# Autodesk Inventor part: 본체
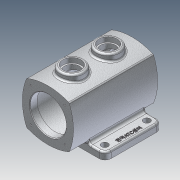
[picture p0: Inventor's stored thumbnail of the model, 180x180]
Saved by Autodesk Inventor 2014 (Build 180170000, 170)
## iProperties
Created: 2013-02
Part Number: 본체
Document SubType Name: Modeling
Designer: 한국산업디자인학원[gmhk.co.kr]
Density: 1 g/cm^3
Material: 일반
Appearance: _시험_알루미늄 표면거칠기
Author: 한국산업디자인학원[gmhk.co.kr]
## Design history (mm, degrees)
sketch "스케치1"
  geometry: L1 (-65, 55)-(65, 55); L2 (65, 55)-(65, -40); L3 (65, -40)-(-65, -40); L4 (-65, -40)-(-65, 55); 2 further points
  constraints: 8 end point, 2 parallel, 1 horizontal, 1 midpoint, 1 perpendicular, 1 vertical alignment
  dimensions: "d0" = 130 distance of L2.end L3.end; "d1" = 95 distance of L1.end L2.end; "d47" = 40 distance from line of L3 point (0, 0)
extrude "돌출1" new body sketch "스케치1" distance "d2" = 12; taper "d3" = 0 deg
sketch "스케치2"
  geometry: L1 (-35.355, 85.355)-(35.355, 85.355); L2 (35.355, 85.355)-(35.355, 14.645); L3 (35.355, 14.645)-(-35.355, 14.645); L4 (-35.355, 14.645)-(-35.355, 85.355); L5 (35.355, 85.355)-(-35.355, 14.645); L6 (65, 0)-(-65, 0) reference; A1 r 91.05 centre (0, 1.45) between (35.355, 85.355) and (-35.355, 85.355); A2 r 91.05 centre (-48.55, 50) between (35.355, 14.645) and (35.355, 85.355); A3 r 91.05 centre (0, 98.55) between (-35.355, 14.645) and (35.355, 14.645); A4 r 91.05 centre (48.55, 50) between (-35.355, 85.355) and (-35.355, 14.645); 3 further points
  constraints: 10 end point, 8 point on circle, 4 centre point, 3 equal radius, 2 midpoint, 2 parallel, 2 perpendicular, 1 horizontal, 1 vertical alignment
  dimensions: "d4" = 50 distance from line of point (0, 50) L6; "d5" = 50 distance of L1.start point (0, 50); "d6" = 85 dimension on A2 A4
extrude "돌출2" join sketch "스케치2" stored distance "d7" = 140; taper "d8" = 0 deg
sketch "스케치3"
  geometry: L1 (28.27, 12)-(65, 12) reference; L2 (-65, 12)-(-28.27, 12) reference; A1 r 91.05 centre (0, 98.55) between (-35.355, 14.645) and (35.355, 14.645) reference; A2 r 91.05 centre (48.55, 50) between (-35.355, 85.355) and (-35.355, 14.645) reference; A3 r 91.05 centre (-48.55, 50) between (35.355, 14.645) and (35.355, 85.355) reference; A4 r 5 centre (-41.653, 17) between (-41.653, 12) and (-36.957, 18.718); A5 r 5 centre (41.653, 17) between (36.957, 18.718) and (41.653, 12); 1 further point
  constraints: 6 point on circle, 4 tangent, 2 centre point, 2 point on line, 1 equal radius
  dimensions: "d9" = 5 radius of A5
extrude "돌출3" join sketch "스케치3" stored distance "d10" = 120; taper "d11" = 0 deg
fillet "모깎기1" dims "d12" = 3
fillet "모깎기2" dims "d13" = 10
fillet "모깎기3" dims "d14" = 3
sketch "스케치4"
  geometry: L1 (-70, 84.185)-(-70, 85.839) reference; L2 (-70, 15.815)-(-70, 84.185) reference; L3 (-70, 14.161)-(-70, 15.815) reference; L4 (-70, 14.161)-(-70, 14.161) reference; L5 (-70, 15.815)-(-70, 14.161) reference; L6 (-70, 84.185)-(-70, 15.815) reference; L7 (-70, 85.839)-(-70, 84.185) reference; L8 (-70, 85.839)-(-70, 85.839) reference; L9 (70, 15.815)-(70, 14.161) reference; L10 (70, 84.185)-(70, 15.815) reference; L11 (70, 85.839)-(70, 84.185) reference; L12 (70, 85.839)-(70, 85.839) reference; L13 (70, 84.185)-(70, 85.839) reference; L14 (70, 15.815)-(70, 84.185) reference; L15 (70, 14.161)-(70, 15.815) reference; L16 (70, 14.161)-(70, 14.161) reference; L17 (-70, 50)-(70, 50); L18 (-70, 80)-(-58, 80); L19 (-58, 80)-(-58, 87.5); L20 (-58, 87.5)-(58, 87.5); L21 (58, 87.5)-(58, 80); L22 (58, 80)-(70, 80); 1 further point
  constraints: 12 end point, 2 collinear, 2 midpoint, 2 parallel, 2 perpendicular, 2 point on line
  dimensions: "d15" = 60 diameter of L18 L17; "d16" = 75 diameter of L20 L17; "d17" = 12 distance of L18.start L18.end; "d18" = 12 distance of L21.end L22.end
revolve "회전1" sketch "스케치4" stored, may be unused: angle "d19" = 90 deg
fillet "모깎기4" dims "d20" = 3
node "작업 평면2"
  node "작업 평면1"
sketch "스케치5"
  geometry: C1 r 20 at (0, 30); C2 r 20 at (0, -30); 1 further point
  constraints: 2 centre point, 2 vertical alignment
  dimensions: "d22" = 40 diameter of C1; "d23" = 40 diameter of C2; "d24" = 60 distance of C2.centre C1.centre; "d25" = 30 distance of point (0, 0) C1.centre (= 0.5 x d24)
extrude "돌출4" join sketch "스케치5" stored distance "d26" = 120; taper "d27" = 0 deg
fillet "모깎기5" dims "d28" = 3
hole "구멍1" diameter "d31" = 25; stored, may be unused: countersink angle "d35" = 90 deg, drill point angle "d37" = 118 deg; dims "d29" = 10, "d30" = 10, "d32" = 6, "d33" = 30, "d34" = 8, "d36" = 8
hole "구멍2" diameter "d40" = 25; stored, may be unused: countersink angle "d44" = 90 deg, drill point angle "d46" = 118 deg; dims "d38" = 10, "d39" = 10, "d41" = 6, "d42" = 30, "d43" = 8, "d45" = 8
sketch "스케치6"
  geometry: L1 (65, -30)-(65, 45) reference; 4 further points
  constraints: 1 midpoint, 1 vertical alignment
  dimensions: "d48" = 13 distance from line of point (52, 42.5) L1; "d49" = 70 distance of point (52, -27.5) point (52, 42.5); "d50" = 35 vertical distance of point (65, 7.5) point (52, 42.5) (= 0.5 x d49)
hole "구멍3" sketch "스케치6" at (52, -27.5), (52, 42.5) diameter "d51" = 11; stored, may be unused: countersink angle "d55" = 90 deg, drill point angle "d57" = 118 deg; dims "d52" = 6, "d53" = 30, "d54" = 8, "d56" = 8
sketch "스케치8"
  geometry: L1 (65, -30)-(65, 45) reference; 3 further points
  constraints: 1 horizontal alignment, 1 midpoint, 1 other
  dimensions: "d60" = 8 distance from line of point (57, 7.5) L1
feature "엠보싱2" sketch "스케치8" dims "d0" = 130, "d1" = 95, "d47" = 40, "d61" = 1, "d62" = 0
chamfer "모따기1" distance "d63" = 1; stored, may be unused: second distance "d64" = 2, angle "d65" = 45 deg
sketch "스케치9" dims "d9" = 5, "d75" = 40, "d76" = 360 deg
  geometry: L1 (0, 81)-(0, 50); L2 (0, 50)-(28.284, 78.284); 1 further point
  constraints: 4 end point, 1 vertical, 1 vertical alignment, 1 other
  dimensions: "d66" = 45 deg angle of L2 L1; "d67" = 40 distance of L2.end L1.end
hole "구멍4" sketch "스케치9" at (28.284, 78.284) diameter "d68" = 3.242; stored, may be unused: countersink angle "d72" = 90 deg, drill point angle "d74" = 118 deg; dims "d69" = 8, "d70" = 30, "d71" = 8, "d73" = 10
node "솔리드1"
mirror "대칭1"
pattern_circular "원형 패턴1" dims angle "d76" = 360 deg
mirror "대칭2"
node "투영된 루프1"
node "투영된 루프2"
